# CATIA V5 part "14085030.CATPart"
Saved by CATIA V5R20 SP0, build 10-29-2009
Part number: 14085030
Definition: NONE
Nomenclature: 14085030
Source: Unknown
Description: 14085030
Bounding box of the stored display mesh (mm): x -15 to 60, y -56.5 to 46.401, z -46.6 to 46.6
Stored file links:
  C:\Users\Utente\Desktop\IO LAVORO\3D X SITO CF\X SITO\PLASTICA\RF2\14085030.CATPart
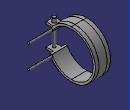
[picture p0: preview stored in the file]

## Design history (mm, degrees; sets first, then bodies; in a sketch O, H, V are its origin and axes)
Body1 "14085030" (main body)
  Solid1: solid without history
